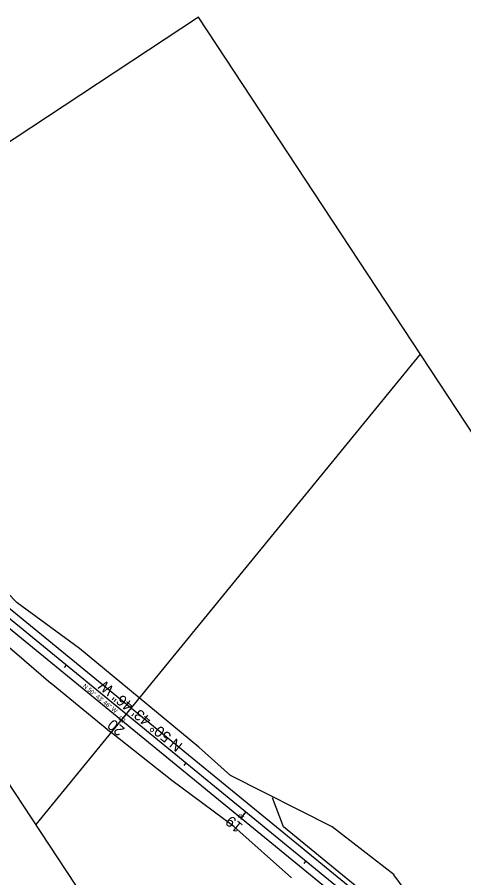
# Model space of a CAD drawing. Extents: x 2399886 to 2513208, y 556821 to 592417.
# Drawn here: x 2446330 to 2446619, y 557640 to 558196 of the extents above; entities that cross this region are included whole.
import ezdxf

# ---------------------------------------------------------------- set-up
doc = ezdxf.new("R2010")
doc.units = 0
for name, color, linetype in [('GM_X_Corporation_Text', 7, 'Continuous'), ('GM_X_Interchange_Ramps', 7, 'Continuous'), ('GM_X_Major_River', 7, 'Continuous'), ('GM_X_Major_River_Text', 7, 'Continuous'), ('GM_X_Section', 7, 'Continuous'), ('SH_Data', 7, 'Continuous')]:
    doc.layers.add(name, color=color, linetype=linetype)

msp = doc.modelspace()

# ---------------------------------------------------------------- linework, layer by layer
at = {"layer": 'GM_X_Corporation_Text'}
for p, q in [((2446502.11, 557672.88), (2446495.03, 557691.59)), ((2446560.53, 557625.12), (2446502.11, 557672.88))]:
    msp.add_line(p, q, dxfattribs=at)
at = {"layer": 'GM_X_Interchange_Ramps'}
for p, q in [((2446329.92, 557817.56), (2446294.06, 557854.44)), ((2446370.25, 557788.23), (2446329.92, 557817.56)), ((2446351.73, 557765.57), (2446313.62, 557798.17)), ((2446408.8, 557756.19), (2446370.25, 557788.23)), ((2446390.54, 557733.9), (2446351.8, 557765.51)), ((2446447.43, 557724.35), (2446408.79, 557756.2)), ((2446429.89, 557702.92), (2446390.59, 557733.85)), ((2446467.89, 557706.13), (2446447.43, 557724.35)), ((2446533.5, 557672.89), (2446467.89, 557706.13)), ((2446470.04, 557673.13), (2446429.98, 557702.85)), ((2446507.33, 557640.03), (2446470.04, 557673.13)), ((2446573.51, 557641.88), (2446533.5, 557672.89)), ((2446604.4, 557599.76), (2446573.45, 557641.93))]:
    msp.add_line(p, q, dxfattribs=at)
at = {"layer": 'GM_X_Major_River'}
for p, q in [((2446555.11, 557619.22), (2446126.56, 557969.61)), ((2446400.28, 557745.81), (2446397.11, 557741.94)), ((2446477.69, 557682.51), (2446474.53, 557678.64))]:
    msp.add_line(p, q, dxfattribs=at)
at = {"layer": 'GM_X_Major_River_Text'}
for p, q in [((2446447.02, 558196.03), (2446212.06, 558041.19)), ((2447217.41, 557027.06), (2446447.02, 558196.03)), ((2446590.45, 557978.4), (2446341.93, 557674.45)), ((2446904.5, 556820.84), (2446234.03, 557838.18))]:
    msp.add_line(p, q, dxfattribs=at)
at = {"layer": 'GM_X_Section'}
for p, q in [((2446558.5, 557622.9), (2446129.72, 557973.48)), ((2446551.72, 557615.53), (2446123.39, 557965.74))]:
    msp.add_line(p, q, dxfattribs=at)
at = {"layer": 'SH_Data'}
for p, q in [((2446555.11, 557619.22), (2446126.56, 557969.61)), ((2446361.57, 557777.46), (2446360.3, 557775.91)), ((2446400.28, 557745.81), (2446399.01, 557744.26)), ((2446438.98, 557714.16), (2446437.72, 557712.61)), ((2446477.69, 557682.51), (2446476.43, 557680.97)), ((2446516.4, 557650.86), (2446515.13, 557649.32))]:
    msp.add_line(p, q, dxfattribs=at)

# ---------------------------------------------------------------- texts
at = {"layer": 'GM_X_Major_River'}
for s, p in [('N 50%%d 43\' 46" W', (2446437.36, 557726.24)), ('20', (2446399.99, 557736.36)), ('19', (2446476.27, 557673.99))]:
    msp.add_text(s, height=7, rotation=140.7295, dxfattribs=at).set_placement(p)
at = {"layer": 'SH_Data'}
for s, rotation, p in [('N 50%%d 43\' 46" W', 320.7295, (2446372.08, 557763.44)), ('20', 140.7295, (2446400.16, 557742.03)), ('19', 140.7295, (2446477.12, 557679.1))]:
    msp.add_text(s, height=2.8, rotation=rotation, dxfattribs=at).set_placement(p)

doc.saveas('drawing.dxf')
